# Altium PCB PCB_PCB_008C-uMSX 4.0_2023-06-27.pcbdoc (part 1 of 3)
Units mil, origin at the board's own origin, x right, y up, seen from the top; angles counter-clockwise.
Board outline 14478.11 x 5217.07 mil, 2 copper layers (Top Layer, Bottom Layer); 184 components, 339 nets, 1501 pads, 946 vias.
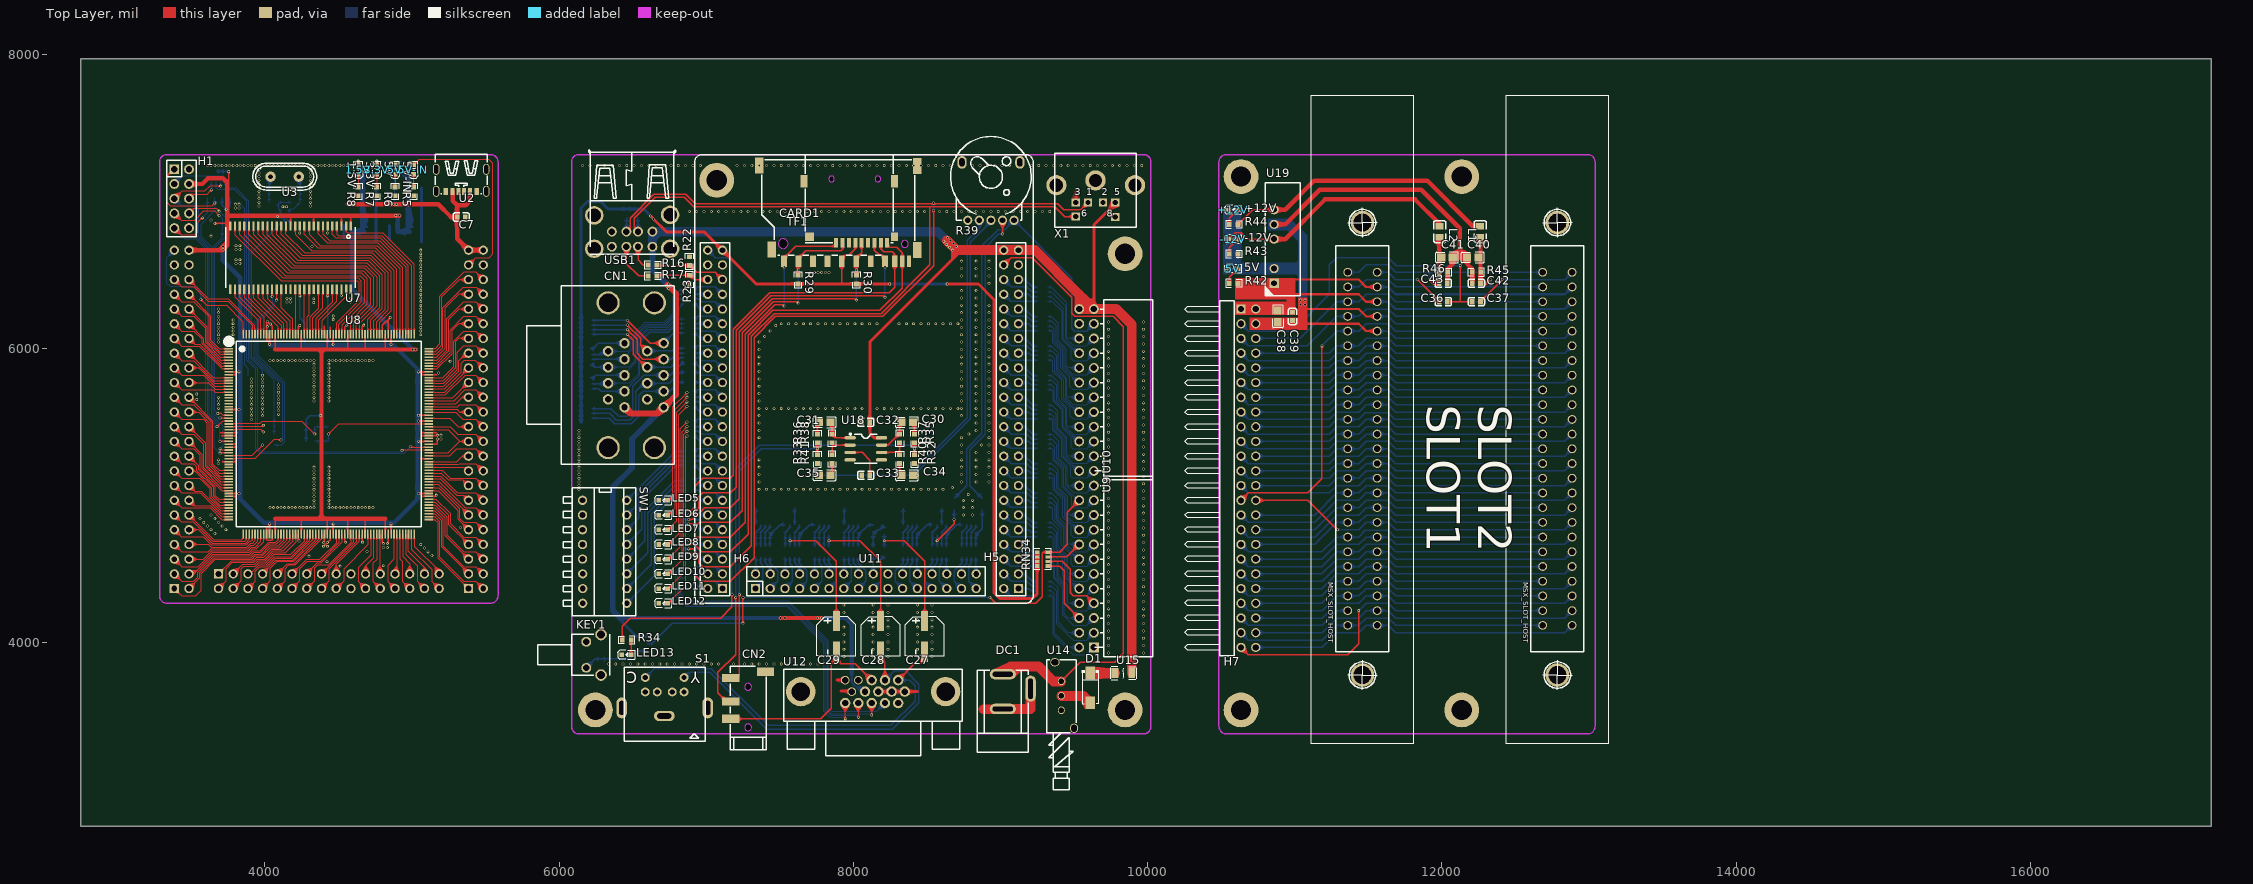
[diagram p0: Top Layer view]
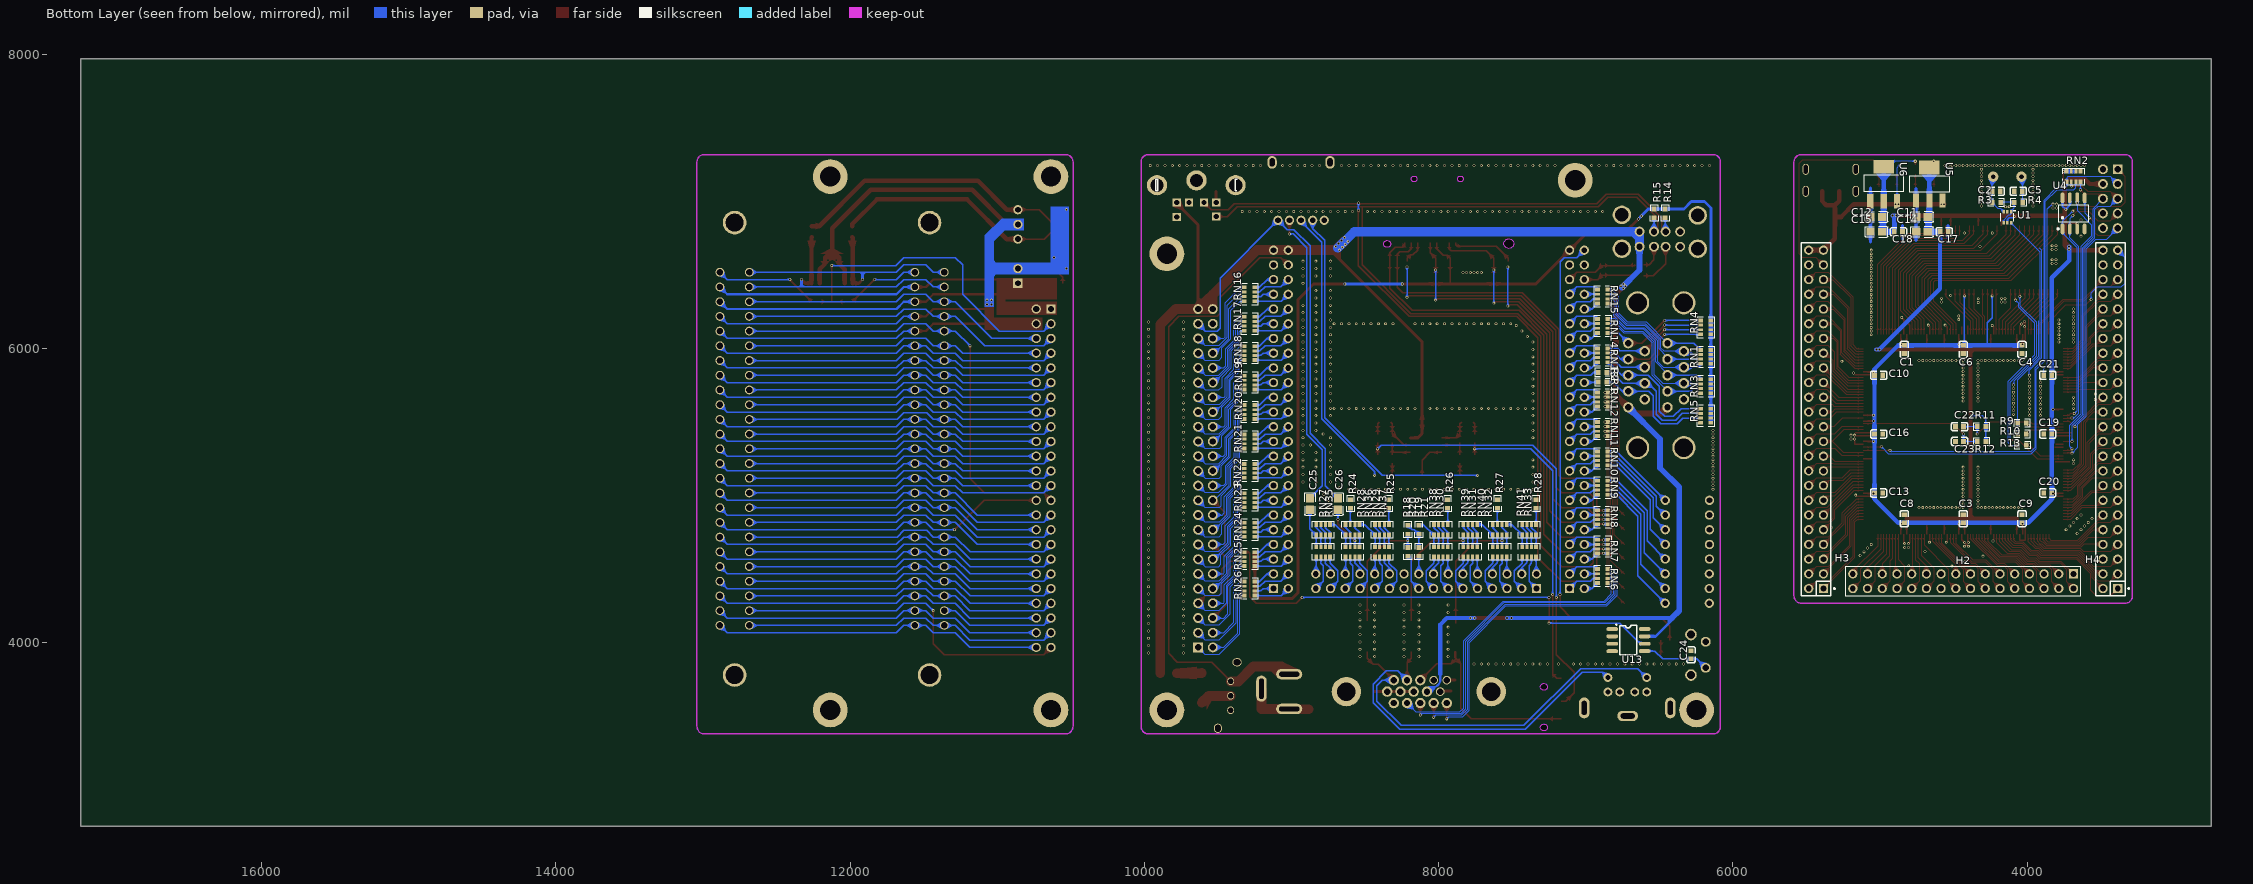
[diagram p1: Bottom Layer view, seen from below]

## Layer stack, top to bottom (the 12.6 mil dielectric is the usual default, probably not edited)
Top Layer: signal copper (thickness not stored)
Dielectric: dielectric 12.6, FR-4, Dk 4.8
Bottom Layer: signal copper (thickness not stored)

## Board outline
17228.11,2750 2750,2750 2750,7967.07 17228.11,7967.07

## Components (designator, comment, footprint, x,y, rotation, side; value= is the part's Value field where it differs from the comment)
1.5V "LED_0603-R" LED_0603 4635,7217.05 r90 top
3.3V "LED_0603-R" LED_0603 4760,7217.05 r90 top
5V "LED_0603-R" LED_0603 4885,7217.05 r90 top
5V "LED_0603-R" LED_0603 10585,6542.05 r0 top
5V-IN "LED_0603-R" LED_0603 5010,7217.05 r90 top
+12V "LED_0603-R" LED_0603 10585,6942.05 r0 top
-12V "LED_0603-R" LED_0603 10585,6742.05 r0 top
C1 "CC0603KRX7R9BB104" C0603 4835,5992.05 r90 bottom
C2 "CC0603JRNPO9BN270" C0603 4210,7067.05 r0 bottom
C3 "CC0603KRX7R9BB104" C0603 4435,4842.05 r270 bottom
C4 "CC0603KRX7R9BB104" C0603 4035,5992.05 r90 bottom
C5 "CC0603JRNPO9BN270" C0603 4060,7067.05 r180 bottom
C6 "CC0603KRX7R9BB104" C0603 4435,5992.05 r90 bottom
C7 "0603B104K500NT" C0603 5335,6892.05 r180 top
C8 "CC0603KRX7R9BB104" C0603 4835,4842.05 r270 bottom
C9 "CC0603KRX7R9BB104" C0603 4035,4842.05 r270 bottom
C10 "CC0603KRX7R9BB104" C0603 5010,5817.05 r0 bottom
C11 "CL21A476MQYNNNE" C0805 4715,6892.05 r180 bottom
C12 "CL21A476MQYNNNE" C0805 5025,6892.05 r180 bottom
C13 "CC0603KRX7R9BB104" C0603 5010,5017.05 r0 bottom
C14 "CL21A476MQYNNNE" C0805 4715,6792.05 r180 bottom
C15 "CL21A476MQYNNNE" C0805 5025,6792.05 r180 bottom
C16 "CC0603KRX7R9BB104" C0603 5010,5417.05 r0 bottom
C17 "0603B104K500NT" C0603 4565,6792.05 r0 bottom
C18 "0603B104K500NT" C0603 4875,6792.05 r0 bottom
C19 "CC0603KRX7R9BB104" C0603 3860,5417.05 r180 bottom
C20 "CC0603KRX7R9BB104" C0603 3860,5017.05 r180 bottom
C21 "CC0603KRX7R9BB104" C0603 3860,5817.05 r180 bottom
C22 "0.1UF" C0603 4460,5467.05 r0 bottom
C23 "0.1UF" C0603 4460,5367.05 r0 bottom
C24 "UMK107BBJ225KA-T" C0603 6285,3917.05 r90 bottom
C25 "CL21A476MQYNNNE" C0805 8875,4942.05 r270 bottom
C26 "CL21A476MQYNNNE" C0805 8685,4942.05 r270 bottom
C27 "固态电容220uF/10V6.3*5.4" CAP-SMD_BD6.3-L6.6-W6.6-LS7.2-FD 8485,4042.05 r270 top
C28 "固态电容220uF/10V6.3*5.4" CAP-SMD_BD6.3-L6.6-W6.6-LS7.2-FD 8185,4042.05 r270 top
C29 "固态电容220uF/10V6.3*5.4" CAP-SMD_BD6.3-L6.6-W6.6-LS7.2-FD 7885,4042.05 r270 top
C30 "CL21A476MQYNNNE" C0805 8365,5497.05 r0 top
C31 "CL21A476MQYNNNE" C0805 7805,5497.05 r0 top
C32 "CC0603KRX7R9BB104" C0603 8085,5497.05 r0 top
C33 "CC0603KRX7R9BB104" C0603 8085,5137.05 r180 top
C34 "CL21A476MQYNNNE" C0805 8365,5137.05 r0 top
C35 "CL21A476MQYNNNE" C0805 7805,5137.05 r0 top
C36 "CAP_0603" C0603 12010,6317.05 r180 top
C37 "CAP_0603" C0603 12235,6317.05 r0 top
C38 "CL21A476MQYNNNE" C0805 10885,6217.05 r90 top
C39 "CAP_0603" C0603 10985,6217.05 r90 top
C40 "CL21A476MQYNNNE" C0805 12210,6617.05 r0 top
C41 "CL21A476MQYNNNE" C0805 12035,6617.05 r0 top
C42 "CAP_0603" C0603 12235,6442.05 r0 top
C43 "CAP_0603" C0603 12010,6442.05 r180 top
CARD1 "SD-101" SD-SMD_SD-101 7897.01,6917.05 r180 top
CN1 "HYC33-VGA18A-158" DSUB-TH_HYC33-VGA18A-158 6522.01,5817.05 r270 top
CN2 "PJ-320D_C431535" AUDIO-SMD_PJ-320D 7285,3642.05 r180 top
D1 "SS14_C2480" SMA_L4.2-W2.6-LS5.3-RD 9610,3692.05 r270 top
DC1 "DC-005" DC-IN-TH_DC-005-A 9110,3667.05 r90 top
H1 "排母2.54mm2*5p 直" HDR-TH_10P-P2.54-V-F-R2-C5-S2.54 3435,7017.05 r270 top
H2 "B-2100S32P-B110" HDR-TH_32P-P2.54-V-M-R2-C16-S2.54 4435,4417.05 r0 bottom
H3 "X6521WV-2x24H-C60D30" HDR-TH_48P-2.54-V-M-R2-C24-S2.54 5435,5517.05 r90 bottom
H4 "X6521WV-2x24H-C60D30" HDR-TH_48P-2.54-V-M-R2-C24-S2.54 3435,5517.05 r90 bottom
H5 "X5521FV-2x24-C70D30-1000" HDR-TH_48P-P2.54-V-F-R2-C24-S2.54 9072.01,5517.05 r90 top
H6 "X5521FV-2x24-C70D30-1000" HDR-TH_48P-P2.54-V-F-R2-C24-S2.54 7060,5517.05 r90 top
H7 "X6521WR-2x24H-C30D60" HDR-TH_48P-P2.54-H-M-R2-C24-S2.54 10685,5117.05 r270 top
KEY1 "1-1825027-1" KEY-TH_1-1825027-1 6235,3917.05 r270 top
L1 "A-6-9007-2" L0805 12260,6792.05 r270 top
L2 "A-6-9007-2" L0805 11985,6792.05 r270 top
LED5 "LED_0603-R" LED_0603 6710,4967.05 r0 top
LED6 "LED_0603-R" LED_0603 6710,4867.05 r0 top
LED7 "LED_0603-R" LED_0603 6710,4767.05 r0 top
LED8 "LED_0603-R" LED_0603 6710,4667.05 r0 top
LED9 "LED_0603-R" LED_0603 6710,4567.05 r0 top
LED10 "LED_0603-R" LED_0603 6710,4467.05 r0 top
LED11 "LED_0603-R" LED_0603 6710,4367.05 r0 top
LED12 "LED_0603-R" LED_0603 6710,4267.05 r0 top
LED13 "LED_0603-R" LED_0603 6460,3917.05 r0 top
R1 "Res_0603" R0603 6885,5772.05 r0 bottom
R2 "Res_0603" R0603 6885,5837.05 r0 bottom
R3 "0603WAF1004T5E" R0603 4210,6992.05 r180 bottom
R4 "0603WAF1000T5E" R0603 4060,6992.05 r0 bottom
R5 "0603WAF3301T5E" R0603_NEW 5010,7067.05 r270 top
R6 "0603WAF3301T5E" R0603_NEW 4885,7067.05 r270 top
R7 "0603WAF3301T5E" R0603_NEW 4760,7067.05 r270 top
R8 "0603WAF3301T5E" R0603_NEW 4635,7067.05 r270 top
R9 "0603WAF1000T5E" R0603 4035,5492.05 r180 bottom
R10 "0603WAF1000T5E" R0603 4035,5417.05 r180 bottom
R11 "0603WAF1000T5E" R0603 4310,5467.05 r180 bottom
R12 "0603WAF1000T5E" R0603 4310,5367.05 r180 bottom
R13 "Res_0603" R0603 4035,5342.05 r0 bottom
R14 "0603WAF1001T5E" R0603 6460,6917.05 r90 bottom
R15 "0603WAF1001T5E" R0603 6535,6917.05 r90 bottom
R16 "0603WAF330JT5E" R0603 6635,6567.05 r180 top
R17 "0603WAF330JT5E" R0603 6635,6492.05 r180 top
R18 "Res_0603" R0603 8210,4617.05 r90 bottom
R19 "Res_0603" R0603 8135,4617.05 r90 bottom
R20 "Res_0603" R0603 8210,4767.05 r90 bottom
R21 "Res_0603" R0603 8135,4767.05 r90 bottom
R22 "0603WAF1502T5E" R0603 6885,6592.05 r270 top
R23 "0603WAF1502T5E" R0603 6885,6467.05 r90 top
R24 "0603WAF1000T5E" R0603 8600,4942.05 r90 bottom
R25 "0603WAF1000T5E" R0603 8340,4942.05 r90 bottom
R26 "0603WAF1000T5E" R0603 7940,4942.05 r90 bottom
R27 "0603WAF1000T5E" R0603 7600,4942.05 r90 bottom
R28 "0603WAF1000T5E" R0603 7340,4942.05 r90 bottom
R29 "0603WAF1002T5E" R0603 7625,6467.05 r270 top
R30 "0603WAF1002T5E" R0603 8020,6467.05 r270 top
R32 "0603WAF1002T5E" R0603 8415,5247.05 r270 top
R33 "0603WAF1002T5E" R0603 7755,5247.05 r270 top
R34 "0603WAF1001T5E" R0603 6460,4017.05 r0 top
R35 "0603WAF100JT5E" R0603 8415,5387.05 r270 top
R36 "0603WAF100JT5E" R0603 7755,5387.05 r270 top
R37 "0603WAF1502T5E" R0603 8315,5387.05 r90 top
R38 "0603WAF1502T5E" R0603 7855,5387.05 r90 top
R39 "RK10J12E0024" RES-TH_RK10J12E002L 8935,7067.05 r0 top
R40 "0603WAF1002T5E" R0603 8315,5247.05 r270 top
R41 "0603WAF1002T5E" R0603 7855,5247.05 r90 top
R42 "0603WAF1001T5E" R0603 10585,6442.05 r180 top
R43 "0603WAF1001T5E" R0603 10585,6642.05 r180 top
R44 "0603WAF1001T5E" R0603 10585,6842.05 r180 top
R45 "0603WAF2001T5E" R0603 12235,6517.05 r0 top
R46 "0603WAF2001T5E" R0603 12010,6517.05 r180 top
RN1 "4D03WGJ0101T5E" RES-ARRAY-SMD_0603-8P-L3.2-W1.6-BL 6185,5942.05 r90 bottom
RN2 "4D03WGJ0101T5E" RES-ARRAY-SMD_0603-8P-L3.2-W1.6-BL 3685,7167.05 r180 bottom
RN3 "4D03WGJ0101T5E" RES-ARRAY-SMD_0603-8P-L3.2-W1.6-BL 6185,5742.05 r90 bottom
RN4 "4D03WGJ0101T5E" RES-ARRAY-SMD_0603-8P-L3.2-W1.6-BL 6185,6142.05 r270 bottom
RN5 "4D03WGJ0101T5E" RES-ARRAY-SMD_0603-8P-L3.2-W1.6-BL 6185,5542.05 r270 bottom
RN6 "4D03WGJ0101T5E" RES-ARRAY-SMD_0603-8P-L3.2-W1.6-BL 6885,4452.05 r270 bottom
RN7 "4D03WGJ0101T5E" RES-ARRAY-SMD_0603-8P-L3.2-W1.6-BL 6885,4652.05 r270 bottom
RN8 "4D03WGJ0101T5E" RES-ARRAY-SMD_0603-8P-L3.2-W1.6-BL 6885,4852.05 r270 bottom
RN9 "4D03WGJ0101T5E" RES-ARRAY-SMD_0603-8P-L3.2-W1.6-BL 6885,5052.05 r270 bottom
RN10 "4D03WGJ0101T5E" RES-ARRAY-SMD_0603-8P-L3.2-W1.6-BL 6885,5252.05 r270 bottom
RN11 "4D03WGJ0101T5E" RES-ARRAY-SMD_0603-8P-L3.2-W1.6-BL 6885,5452.05 r270 bottom
RN12 "4D03WGJ0101T5E" RES-ARRAY-SMD_0603-8P-L3.2-W1.6-BL 6885,5652.05 r270 bottom
RN13 "4D03WGJ0101T5E" RES-ARRAY-SMD_0603-8P-L3.2-W1.6-BL 6885,5952.05 r270 bottom
RN14 "4D03WGJ0101T5E" RES-ARRAY-SMD_0603-8P-L3.2-W1.6-BL 6885,6152.05 r270 bottom
RN15 "4D03WGJ0101T5E" RES-ARRAY-SMD_0603-8P-L3.2-W1.6-BL 6885,6352.05 r270 bottom
RN16 "4D03WGJ0101T5E" RES-ARRAY-SMD_0603-8P-L3.2-W1.6-BL 9285,6367.05 r90 bottom
RN17 "4D03WGJ0101T5E" RES-ARRAY-SMD_0603-8P-L3.2-W1.6-BL 9285,6167.05 r90 bottom
RN18 "4D03WGJ0101T5E" RES-ARRAY-SMD_0603-8P-L3.2-W1.6-BL 9285,5967.05 r90 bottom
RN19 "4D03WGJ0101T5E" RES-ARRAY-SMD_0603-8P-L3.2-W1.6-BL 9285,5767.05 r90 bottom
RN20 "4D03WGJ0101T5E" RES-ARRAY-SMD_0603-8P-L3.2-W1.6-BL 9285,5567.05 r90 bottom
RN21 "4D03WGJ0101T5E" RES-ARRAY-SMD_0603-8P-L3.2-W1.6-BL 9285,5367.05 r90 bottom
RN22 "4D03WGJ0101T5E" RES-ARRAY-SMD_0603-8P-L3.2-W1.6-BL 9285,5167.05 r90 bottom
RN23 "4D03WGJ0101T5E" RES-ARRAY-SMD_0603-8P-L3.2-W1.6-BL 9285,4967.05 r90 bottom
RN24 "4D03WGJ0101T5E" RES-ARRAY-SMD_0603-8P-L3.2-W1.6-BL 9285,4767.05 r90 bottom
RN25 "4D03WGJ0101T5E" RES-ARRAY-SMD_0603-8P-L3.2-W1.6-BL 9285,4567.05 r90 bottom
RN26 "4D03WGJ0101T5E" RES-ARRAY-SMD_0603-8P-L3.2-W1.6-BL 9285,4367.05 r90 bottom
RN27 "4D03WGJ0101T5E" RES-ARRAY-SMD_0603-8P-L3.2-W1.6-BL 8785,4617.05 r180 bottom
RN28 "4D03WGJ0101T5E" RES-ARRAY-SMD_0603-8P-L3.2-W1.6-BL 8585,4617.05 r180 bottom
RN29 "4D03WGJ0101T5E" RES-ARRAY-SMD_0603-8P-L3.2-W1.6-BL 8385,4617.05 r180 bottom
RN30 "4D03WGJ0101T5E" RES-ARRAY-SMD_0603-8P-L3.2-W1.6-BL 7985,4617.05 r180 bottom
RN31 "4D03WGJ0101T5E" RES-ARRAY-SMD_0603-8P-L3.2-W1.6-BL 7785,4617.05 r180 bottom
RN32 "4D03WGJ0101T5E" RES-ARRAY-SMD_0603-8P-L3.2-W1.6-BL 7585,4617.05 r180 bottom
RN33 "4D03WGJ0101T5E" RES-ARRAY-SMD_0603-8P-L3.2-W1.6-BL 7385,4617.05 r180 bottom
RN34 "4D03WGJ0101T5E" RES-ARRAY-SMD_0603-8P-L3.2-W1.6-BL 9285,4567.05 r90 top
RN35 "4D03WGJ0101T5E" RES-ARRAY-SMD_0603-8P-L3.2-W1.6-BL 8785,4767.05 r180 bottom
RN36 "4D03WGJ0101T5E" RES-ARRAY-SMD_0603-8P-L3.2-W1.6-BL 8585,4767.05 r180 bottom
RN37 "4D03WGJ0101T5E" RES-ARRAY-SMD_0603-8P-L3.2-W1.6-BL 8385,4767.05 r180 bottom
RN38 "4D03WGJ0101T5E" RES-ARRAY-SMD_0603-8P-L3.2-W1.6-BL 7985,4767.05 r180 bottom
RN39 "4D03WGJ0101T5E" RES-ARRAY-SMD_0603-8P-L3.2-W1.6-BL 7785,4767.05 r180 bottom
RN40 "4D03WGJ0101T5E" RES-ARRAY-SMD_0603-8P-L3.2-W1.6-BL 7585,4767.05 r180 bottom
RN41 "4D03WGJ0101T5E" RES-ARRAY-SMD_0603-8P-L3.2-W1.6-BL 7385,4767.05 r180 bottom
S1 "S端子母座" S端子母座 6710,3567.05 r180 top
SLOT1 "MSX_SLOT_HOST" CONN_EDGE_50P 11460,5317.05 r270 top
SLOT2 "MSX_SLOT_HOST" CONN_EDGE_50P 12785,5317.05 r270 top
SW1 "DP-08BP" SW-TH_DP-08XP 6310,4617.05 r270 top
TF1 "TF-012" TF-SMD_TF-012 7972.01,6927.05 r180 top
U1 "NC7WZU04P6X" SC-70-6_L2.2-W1.3-P0.65-LS2.1-BR 4135,6892.05 r90 bottom
U2 "USB-TYPE-C-009" TYPE-C-SMD_TYPE-C-6P 5335,7142.05 r180 top
U3 "ECS-214.7-S-4" HC-49US_L11.0-W4.6-P4.88 4135,7167.05 r180 top
U4 "EPCS4-SO8" SOP-8_L4.9-W3.9-P1.27-LS6.0-BL 3685,6917.05 r180 bottom
U5 "AMS1117-1.5_C963403" SOT-223_L6.3-W3.5-P2.30-LS7.0-BR 4665,7117.05 r270 bottom
U6 "AMS1117-3.3_C6186" SOT-223-3_L6.5-W3.4-P2.30-LS7.0-BR 4975,7117.05 r270 bottom
U7 "MT48LC16M" TSOP54 4175,6617.05 r180 top
U8 "EP1C12Q240C8N" MQFP-240_L32.0-W32.0-P0.50-LS34.6-BL 4435,5417.05 r270 top
U9 "PM254-2-12-W-8.5" HDR-TH_24P-P2.54-H-F-R2-C12-W8.5 9585,4517.05 r90 top
U10 "PM254-2-12-W-8.5" hdr-th_24p-p2.54-h-f-r2-c12-w8.5 9585,5717.05 r90 top
U11 "PM254-2-16-Z-8.5" HDR-TH_32P-P2.54-V-F-R2-C16-S2.54 8085,4417.05 r0 top
U12 "VGAS-C" DB15-TH_FDB1519-F0DB300U1KA 8135,3667.05 r0 top
U13 "M51953BFP" SOP-8_L4.9-W3.8-P1.27-LS6.0-BL 6710,4017.05 r270 bottom
U14 "PS-12E051" SW-TH_PS-12E051XX 9435,3642.05 r270 top
U15 "PTC1206SMD1206P010TF0.1A/60V" F1206 9835,3792.05 r0 top
U18 "TPA6111A2DR" SOIC-8_L5.0-W4.0-P1.27-LS6.0-BL 8085,5317.05 r270 top
U19 "A0512S-1W" PWRM-TH_7P-L19.5-W6.0-P2.54-PE3_7 10860,6692.05 r90 top
USB1 "907-111A1022D10200" USB-A-TH_USB-M-51 6497.01,6792.05 r180 top
X1 "MINI_DIN_6" M_DIN6 9647.01,7017.05 r0 top

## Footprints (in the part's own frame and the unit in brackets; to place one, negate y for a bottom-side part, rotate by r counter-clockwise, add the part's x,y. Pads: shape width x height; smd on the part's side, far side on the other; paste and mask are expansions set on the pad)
AUDIO-SMD_PJ-320D [mm]
  rect 3x1.4 smd: 1(-3,-4.05) 2(3,4.05) 3(3,1.05) 4(3,-2.95)
  Multi-Layer board cut-out: -0.6,-1.45 -0.518,-1.748 -0.298,-1.965 0,-2.045 0.298,-1.965 0.518,-1.748 0.6,-1.45 0.6,-1.45 0.518,-1.152 0.298,-0.935 0,-0.856 -0.298,-0.935 -0.518,-1.152 -0.6,-1.45
  Multi-Layer board cut-out: -0.6,5.55 -0.518,5.252 -0.298,5.035 0,4.955 0.298,5.035 0.518,5.252 0.6,5.55 0.6,5.55 0.518,5.848 0.298,6.065 0,6.144 -0.298,6.065 -0.518,5.848 -0.6,5.55
  Multi-Layer keep-out region: -0.6,-1.45 -0.518,-1.748 -0.298,-1.965 0,-2.045 0.298,-1.965 0.518,-1.748 0.6,-1.45 0.6,-1.45 0.518,-1.152 0.298,-0.935 0,-0.856 -0.298,-0.935 -0.518,-1.152 -0.6,-1.45
  Multi-Layer keep-out region: -0.6,5.55 -0.518,5.252 -0.298,5.035 0,4.955 0.298,5.035 0.518,5.252 0.6,5.55 0.6,5.55 0.518,5.848 0.298,6.065 0,6.144 -0.298,6.065 -0.518,5.848 -0.6,5.55
  silkscreen extent -3.12,-4.98 3.13,9.37
C0603 [mm]
  rect 0.8x0.9 smd: 1(-0.7,0) 2(0.7,0)
  silkscreen extent -1.41,-0.71 1.39,0.72
C0805 [mm]
  rect 1.41x1.35 smd: 1(-1,0) 2(1,0)
  silkscreen extent -1.96,-0.9 1.96,0.9
CAP-SMD_BD6.3-L6.6-W6.6-LS7.2-FD [mm]
  rect 3.5x1.2 smd: 1(-2.67,0) 2(2.67,0)
  silkscreen extent -3.38,-3.38 3.38,3.38
CONN_EDGE_50P [mil]
  round 160 hole 120 slot 120.2 at 0 deg: 0(-1537.52,0) 0(1537.47,0)
  round 60 hole 40 slot 40.2 at 0 deg: 1(1199.97,100) 2(1199.97,-100) 3(1099.97,100) 4(1099.97,-100) 5(999.97,100) 6(999.97,-100) 7(899.97,100) 8(899.97,-100) 9(799.97,100) 10(799.97,-100) 11(699.97,100) 12(699.97,-100) 13(599.97,100) 14(599.97,-100) 15(499.97,100) 16(499.97,-100) 17(399.97,100) 18(399.97,-100) 19(299.97,100) 20(299.97,-100) 21(199.97,100) 22(199.97,-100) 23(99.97,100) 24(99.97,-100) 25(-0.03,100) 26(-0.03,-100) 27(-100.02,100) 28(-100.02,-100) 29(-200.02,100) 30(-200.02,-100) 31(-300.02,100) 32(-300.02,-100) 33(-400.02,100) 34(-400.02,-100) 35(-500.02,100) 36(-500.02,-100) 37(-600.02,100) 38(-600.02,-100) 39(-700.02,100) 40(-700.02,-100) 41(-800.02,100) 42(-800.02,-100) 43(-900.02,100) 44(-900.02,-100) 45(-1000.02,100) 46(-1000.02,-100) 47(-1100.02,100) 48(-1100.02,-100) 49(-1200.02,100) 50(-1200.02,-100)
  silkscreen extent -2400,-350 2000,350
DB15-TH_FDB1519-F0DB300U1KA [mm]
  round 5.08 hole 3.2: 0(-12.495,0) 0(12.495,0)
  round 1.8 hole 1.1: 1(4.315,1.98) 2(2.025,1.98) 3(-0.265,1.98) 6(5.46,0) 7(3.17,0) 8(0.88,0) 9(-1.41,0) 11(4.315,-1.98) 12(2.025,-1.98) 13(-0.265,-1.98) 14(-2.555,-1.98) 15(-4.845,-1.98)
  round 1.5 hole 1.1: 4(-2.555,1.98) 5(-4.845,1.98) 10(-3.7,0)
  silkscreen extent -15.4,-11.1 15.4,3.85
DC-IN-TH_DC-005-A [mm]
  oval 1.8x4.5 hole 0.8 slot 3.5 at 90 deg: 1(3,2.4) 2(-3,2.4)
  oval 4.5x1.8 hole 0.8 slot 3.5 at 0 deg: 3(0.5,-2.4)
  silkscreen extent -10.5,-2 3.7,6.8
DSUB-TH_HYC33-VGA18A-158 [mm]
  round 1.8 hole 1.1: 1(-5.54,-1.96) 2(-2.77,-1.96) 3(0,-1.96) 4(2.77,-1.96) 5(5.54,-1.96) 6(-4.155,-4.8) 7(-1.385,-4.8) 8(1.385,-4.8) 9(4.155,-4.8) 10(-5.54,4.8) 11(-2.77,4.8) 12(0,4.8) 13(2.77,4.8) 14(5.54,4.8) 15(-4.155,1.96) 16(-1.385,1.96) 17(1.385,1.96) 18(4.155,1.96)
  round 4 hole 3.2: 19(-12.5,3.2) 20(12.5,3.2) 21(-12.5,-4.8) 22(12.5,-4.8)
  silkscreen extent -15.4,-18.9 15.4,6.6
F1206 [mm]
  rect 1.19x1.728 smd: 1(-1.445,0) 2(1.445,0)
  silkscreen extent -2.27,-1.09 2.27,1.09
HC-49US_L11.0-W4.6-P4.88 [mm]
  round 1.8 hole 0.8: 1(-2.44,0) 2(2.44,0)
  silkscreen extent -5.51,-2.32 5.51,2.32
HDR-TH_10P-P2.54-V-F-R2-C5-S2.54 [mm]
  rect 1.575x1.7 hole 1.1: 1(-5.08,-1.27)
  round 1.7 hole 1.1: 2(-5.08,1.27) 3(-2.54,-1.27) 4(-2.54,1.27) 5(0,-1.27) 6(0,1.27) 7(2.54,-1.27) 8(2.54,1.27) 9(5.08,-1.27) 10(5.08,1.27)
  silkscreen extent -6.6,-2.54 6.6,2.54
HDR-TH_24P-P2.54-H-F-R2-C12-W8.5 [mm]
  rect 1.7x1.7 hole 1.1: 1(-13.97,-1.27)
  round 1.7 hole 1.1: 2(-13.97,1.27) 3(-11.43,-1.27) 4(-11.43,1.27) 5(-8.89,-1.27) 6(-8.89,1.27) 7(-6.35,-1.27) 8(-6.35,1.27) 9(-3.81,-1.27) 10(-3.81,1.27) 11(-1.27,-1.27) 12(-1.27,1.27) 13(1.27,-1.27) 14(1.27,1.27) 15(3.81,-1.27) 16(3.81,1.27) 17(6.35,-1.27) 18(6.35,1.27) 19(8.89,-1.27) 20(8.89,1.27) 21(11.43,-1.27) 22(11.43,1.27) 23(13.97,-1.27) 24(13.97,1.27)
  silkscreen extent -15.54,-11.43 15.54,-1.4
hdr-th_24p-p2.54-h-f-r2-c12-w8.5 [mm]
  round 1.7 hole 1.1: 1(-13.97,-1.27) 2(-13.97,1.27) 3(-11.43,-1.27) 4(-11.43,1.27) 5(-8.89,-1.27) 6(-8.89,1.27) 7(-6.35,-1.27) 8(-6.35,1.27) 9(-3.81,-1.27) 10(-3.81,1.27) 11(-1.27,-1.27) 12(-1.27,1.27) 13(1.27,-1.27) 14(1.27,1.27) 15(3.81,-1.27) 16(3.81,1.27) 17(6.35,-1.27) 18(6.35,1.27) 19(8.89,-1.27) 20(8.89,1.27) 21(11.43,-1.27) 22(11.43,1.27) 23(13.97,-1.27) 24(13.97,1.27)
  silkscreen extent -15.54,-11.43 15.54,-1.4
HDR-TH_32P-P2.54-V-F-R2-C16-S2.54 [mm]
  rect 1.6x1.6 hole 1: 1(-19.05,-1.27)
  round 1.6 hole 1: 2(-19.05,1.27) 3(-16.51,-1.27) 4(-16.51,1.27) 5(-13.97,-1.27) 6(-13.97,1.27) 7(-11.43,-1.27) 8(-11.43,1.27) 9(-8.89,-1.27) 10(-8.89,1.27) 11(-6.35,-1.27) 12(-6.35,1.27) 13(-3.81,-1.27) 14(-3.81,1.27) 15(-1.27,-1.27) 16(-1.27,1.27) 17(1.27,-1.27) 18(1.27,1.27) 19(3.81,-1.27) 20(3.81,1.27) 21(6.35,-1.27) 22(6.35,1.27) 23(8.89,-1.27) 24(8.89,1.27) 25(11.43,-1.27) 26(11.43,1.27) 27(13.97,-1.27) 28(13.97,1.27) 29(16.51,-1.27) 30(16.51,1.27) 31(19.05,-1.27) 32(19.05,1.27)
  silkscreen extent -20.57,-2.54 20.57,2.54
HDR-TH_32P-P2.54-V-M-R2-C16-S2.54 [mm]
  rect 1.6x1.6 hole 1: 1(-19.05,-1.27)
  round 1.6 hole 1: 2(-19.05,1.27) 3(-16.51,-1.27) 4(-16.51,1.27) 5(-13.97,-1.27) 6(-13.97,1.27) 7(-11.43,-1.27) 8(-11.43,1.27) 9(-8.89,-1.27) 10(-8.89,1.27) 11(-6.35,-1.27) 12(-6.35,1.27) 13(-3.81,-1.27) 14(-3.81,1.27) 15(-1.27,-1.27) 16(-1.27,1.27) 17(1.27,-1.27) 18(1.27,1.27) 19(3.81,-1.27) 20(3.81,1.27) 21(6.35,-1.27) 22(6.35,1.27) 23(8.89,-1.27) 24(8.89,1.27) 25(11.43,-1.27) 26(11.43,1.27) 27(13.97,-1.27) 28(13.97,1.27) 29(16.51,-1.27) 30(16.51,1.27) 31(19.05,-1.27) 32(19.05,1.27)
  silkscreen extent -20.32,-2.54 20.32,2.54
HDR-TH_48P-2.54-V-M-R2-C24-S2.54 [mm]
  rect 1.6x1.6 hole 1: 1(-29.21,-1.27)
  round 1.6 hole 1: 2(-29.21,1.27) 3(-26.67,-1.27) 4(-26.67,1.27) 5(-24.13,-1.27) 6(-24.13,1.27) 7(-21.59,-1.27) 8(-21.59,1.27) 9(-19.05,-1.27) 10(-19.05,1.27) 11(-16.51,-1.27) 12(-16.51,1.27) 13(-13.97,-1.27) 14(-13.97,1.27) 15(-11.43,-1.27) 16(-11.43,1.27) 17(-8.89,-1.27) 18(-8.89,1.27) 19(-6.35,-1.27) 20(-6.35,1.27) 21(-3.81,-1.27) 22(-3.81,1.27) 23(-1.27,-1.27) 24(-1.27,1.27) 25(1.27,-1.27) 26(1.27,1.27) 27(3.81,-1.27) 28(3.81,1.27) 29(6.35,-1.27) 30(6.35,1.27) 31(8.89,-1.27) 32(8.89,1.27) 33(11.43,-1.27) 34(11.43,1.27) 35(13.97,-1.27) 36(13.97,1.27) 37(16.51,-1.27) 38(16.51,1.27) 39(19.05,-1.27) 40(19.05,1.27) 41(21.59,-1.27) 42(21.59,1.27) 43(24.13,-1.27) 44(24.13,1.27) 45(26.67,-1.27) 46(26.67,1.27) 47(29.21,-1.27) 48(29.21,1.27)
  silkscreen extent -30.48,-3.3 30.48,2.54
HDR-TH_48P-P2.54-H-M-R2-C24-S2.54 [mm]
  rect 1.6x1.6 hole 1.05: 1(-29.21,-1.27)
  round 1.6 hole 1.05: 2(-29.21,1.27) 3(-26.67,-1.27) 4(-26.67,1.27) 5(-24.13,-1.27) 6(-24.13,1.27) 7(-21.59,-1.27) 8(-21.59,1.27) 9(-19.05,-1.27) 10(-19.05,1.27) 11(-16.51,-1.27) 12(-16.51,1.27) 13(-13.97,-1.27) 14(-13.97,1.27) 15(-11.43,-1.27) 16(-11.43,1.27) 17(-8.89,-1.27) 18(-8.89,1.27) 19(-6.35,-1.27) 20(-6.35,1.27) 21(-3.81,-1.27) 22(-3.81,1.27) 23(-1.27,-1.27) 24(-1.27,1.27) 25(1.27,-1.27) 26(1.27,1.27) 27(3.81,-1.27) 28(3.81,1.27) 29(6.35,-1.27) 30(6.35,1.27) 31(8.89,-1.27) 32(8.89,1.27) 33(11.43,-1.27) 34(11.43,1.27) 35(13.97,-1.27) 36(13.97,1.27) 37(16.51,-1.27) 38(16.51,1.27) 39(19.05,-1.27) 40(19.05,1.27) 41(21.59,-1.27) 42(21.59,1.27) 43(24.13,-1.27) 44(24.13,1.27) 45(26.67,-1.27) 46(26.67,1.27) 47(29.21,-1.27) 48(29.21,1.27)
  silkscreen extent -30.67,-10.97 30.67,-2.47
HDR-TH_48P-P2.54-V-F-R2-C24-S2.54 [mm]
  rect 1.6x1.6 hole 1: 1(-29.21,-1.27)
  round 1.6 hole 1: 2(-29.21,1.27) 3(-26.67,-1.27) 4(-26.67,1.27) 5(-24.13,-1.27) 6(-24.13,1.27) 7(-21.59,-1.27) 8(-21.59,1.27) 9(-19.05,-1.27) 10(-19.05,1.27) 11(-16.51,-1.27) 12(-16.51,1.27) 13(-13.97,-1.27) 14(-13.97,1.27) 15(-11.43,-1.27) 16(-11.43,1.27) 17(-8.89,-1.27) 18(-8.89,1.27) 19(-6.35,-1.27) 20(-6.35,1.27) 21(-3.81,-1.27) 22(-3.81,1.27) 23(-1.27,-1.27) 24(-1.27,1.27) 25(1.27,-1.27) 26(1.27,1.27) 27(3.81,-1.27) 28(3.81,1.27) 29(6.35,-1.27) 30(6.35,1.27) 31(8.89,-1.27) 32(8.89,1.27) 33(11.43,-1.27) 34(11.43,1.27) 35(13.97,-1.27) 36(13.97,1.27) 37(16.51,-1.27) 38(16.51,1.27) 39(19.05,-1.27) 40(19.05,1.27) 41(21.59,-1.27) 42(21.59,1.27) 43(24.13,-1.27) 44(24.13,1.27) 45(26.67,-1.27) 46(26.67,1.27) 47(29.21,-1.27) 48(29.21,1.27)
  silkscreen extent -30.48,-2.54 30.48,2.54
KEY-TH_1-1825027-1 [mm]
  round 2 hole 1.4: 0(-3.5,1.27) 0(3.5,1.27)
  round 1.7 hole 1.1: 1(-2.25,-1.27) 2(2.25,-1.27)
  silkscreen extent -3.56,-9.63 3.56,2.79
L0805 [mil]
  rect 44.59x54.21 smd: 1(-38.04,0) 2(38.04,0)
  silkscreen extent -77,-40 73,40
LED_0603 [mil]
  rect 31.5x31.5 smd: 1(-33.5,-0.4) 2(29.5,-0.2)
  silkscreen extent -61,-30 53,30
M_DIN6 [mil]
  rect 56x56 hole 35.4: 1(-52,-26) 2(50,-26) 3(-135,-26) 5(133,-26) 6(-135,-122) 8(133,-124)
  round 137.8 hole 90.6: SH1(267,92) SH2(-1,124) SH3(-267,92)
  silkscreen extent -277,-193 275,309
MQFP-240_L32.0-W32.0-P0.50-LS34.6-BL [mm]
  rect 0.28x1.5 smd: 1(-14.75,-17.25) 2(-14.25,-17.25) 3(-13.75,-17.25) 4(-13.25,-17.25) 5(-12.75,-17.25) 6(-12.25,-17.25) 7(-11.75,-17.25) 8(-11.25,-17.25) 9(-10.75,-17.25) 10(-10.25,-17.25) 11(-9.75,-17.25) 12(-9.25,-17.25) 13(-8.75,-17.25) 14(-8.25,-17.25) 15(-7.75,-17.25) 16(-7.25,-17.25) 17(-6.75,-17.25) 18(-6.25,-17.25) 19(-5.75,-17.25) 20(-5.25,-17.25) 21(-4.75,-17.25) 22(-4.25,-17.25) 23(-3.75,-17.25) 24(-3.25,-17.25) 25(-2.75,-17.25) 26(-2.25,-17.25) 27(-1.75,-17.25) 28(-1.25,-17.25) 29(-0.75,-17.25) 30(-0.25,-17.25) 31(0.25,-17.25) 32(0.75,-17.25) 33(1.25,-17.25) 34(1.75,-17.25) 35(2.25,-17.25) 36(2.75,-17.25) 37(3.25,-17.25) 38(3.75,-17.25) 39(4.25,-17.25) 40(4.75,-17.25) 41(5.25,-17.25) 42(5.75,-17.25) 43(6.25,-17.25) 44(6.75,-17.25) 45(7.25,-17.25) 46(7.75,-17.25) 47(8.25,-17.25) 48(8.75,-17.25) 49(9.25,-17.25) 50(9.75,-17.25) 51(10.25,-17.25) 52(10.75,-17.25) 53(11.25,-17.25) 54(11.75,-17.25) 55(12.25,-17.25) 56(12.75,-17.25) 57(13.25,-17.25) 58(13.75,-17.25) 59(14.25,-17.25) 60(14.75,-17.25) 121(14.75,17.25) 122(14.25,17.25) 123(13.75,17.25) 124(13.25,17.25) 125(12.75,17.25) 126(12.25,17.25) 127(11.75,17.25) 128(11.25,17.25) 129(10.75,17.25) 130(10.25,17.25) 131(9.75,17.25) 132(9.25,17.25) 133(8.75,17.25) 134(8.25,17.25) 135(7.75,17.25) 136(7.25,17.25) 137(6.75,17.25) 138(6.25,17.25) 139(5.75,17.25) 140(5.25,17.25) 141(4.75,17.25) 142(4.25,17.25) 143(3.75,17.25) 144(3.25,17.25) 145(2.75,17.25) 146(2.25,17.25) 147(1.75,17.25) 148(1.25,17.25) 149(0.75,17.25) 150(0.25,17.25) 151(-0.25,17.25) 152(-0.75,17.25) 153(-1.25,17.25) 154(-1.75,17.25) 155(-2.25,17.25) 156(-2.75,17.25) 157(-3.25,17.25) 158(-3.75,17.25) 159(-4.25,17.25) 160(-4.75,17.25) 161(-5.25,17.25) 162(-5.75,17.25) 163(-6.25,17.25) 164(-6.75,17.25) 165(-7.25,17.25) 166(-7.75,17.25) 167(-8.25,17.25) 168(-8.75,17.25) 169(-9.25,17.25) 170(-9.75,17.25) 171(-10.25,17.25) 172(-10.75,17.25) 173(-11.25,17.25) 174(-11.75,17.25) 175(-12.25,17.25) 176(-12.75,17.25) 177(-13.25,17.25) 178(-13.75,17.25) 179(-14.25,17.25) 180(-14.75,17.25)
  rect 1.5x0.28 smd: 61(17.25,-14.75) 62(17.25,-14.25) 63(17.25,-13.75) 64(17.25,-13.25) 65(17.25,-12.75) 66(17.25,-12.25) 67(17.25,-11.75) 68(17.25,-11.25) 69(17.25,-10.75) 70(17.25,-10.25) 71(17.25,-9.75) 72(17.25,-9.25) 73(17.25,-8.75) 74(17.25,-8.25) 75(17.25,-7.75) 76(17.25,-7.25) 77(17.25,-6.75) 78(17.25,-6.25) 79(17.25,-5.75) 80(17.25,-5.25) 81(17.25,-4.75) 82(17.25,-4.25) 83(17.25,-3.75) 84(17.25,-3.25) 85(17.25,-2.75) 86(17.25,-2.25) 87(17.25,-1.75) 88(17.25,-1.25) 89(17.25,-0.75) 90(17.25,-0.25) 91(17.25,0.25) 92(17.25,0.75) 93(17.25,1.25) 94(17.25,1.75) 95(17.25,2.25) 96(17.25,2.75) 97(17.25,3.25) 98(17.25,3.75) 99(17.25,4.25) 100(17.25,4.75) 101(17.25,5.25) 102(17.25,5.75) 103(17.25,6.25) 104(17.25,6.75) 105(17.25,7.25) 106(17.25,7.75) 107(17.25,8.25) 108(17.25,8.75) 109(17.25,9.25) 110(17.25,9.75) 111(17.25,10.25) 112(17.25,10.75) 113(17.25,11.25) 114(17.25,11.75) 115(17.25,12.25) 116(17.25,12.75) 117(17.25,13.25) 118(17.25,13.75) 119(17.25,14.25) 120(17.25,14.75) 181(-17.25,14.75) 182(-17.25,14.25) 183(-17.25,13.75) 184(-17.25,13.25) 185(-17.25,12.75) 186(-17.25,12.25) 187(-17.25,11.75) 188(-17.25,11.25) 189(-17.25,10.75) 190(-17.25,10.25) 191(-17.25,9.75) 192(-17.25,9.25) 193(-17.25,8.75) 194(-17.25,8.25) 195(-17.25,7.75) 196(-17.25,7.25) 197(-17.25,6.75) 198(-17.25,6.25) 199(-17.25,5.75) 200(-17.25,5.25) 201(-17.25,4.75) 202(-17.25,4.25) 203(-17.25,3.75) 204(-17.25,3.25) 205(-17.25,2.75) 206(-17.25,2.25) 207(-17.25,1.75) 208(-17.25,1.25) 209(-17.25,0.75) 210(-17.25,0.25) 211(-17.25,-0.25) 212(-17.25,-0.75) 213(-17.25,-1.25) 214(-17.25,-1.75) 215(-17.25,-2.25) 216(-17.25,-2.75) 217(-17.25,-3.25) 218(-17.25,-3.75) 219(-17.25,-4.25) 220(-17.25,-4.75) 221(-17.25,-5.25) 222(-17.25,-5.75) 223(-17.25,-6.25) 224(-17.25,-6.75) 225(-17.25,-7.25) 226(-17.25,-7.75) 227(-17.25,-8.25) 228(-17.25,-8.75) 229(-17.25,-9.25) 230(-17.25,-9.75) 231(-17.25,-10.25) 232(-17.25,-10.75) 233(-17.25,-11.25) 234(-17.25,-11.75) 235(-17.25,-12.25) 236(-17.25,-12.75) 237(-17.25,-13.25) 238(-17.25,-13.75) 239(-17.25,-14.25) 240(-17.25,-14.75)
  silkscreen extent -16.5,-17.75 16,16
PWRM-TH_7P-L19.5-W6.0-P2.54-PE3_7 [mm]
  rect 1.6x1.6 hole 1: 1(-6.35,0)
  round 1.6 hole 1: 2(-3.81,0) 4(1.27,0) 5(3.81,0) 6(6.35,0)
  silkscreen extent -8.51,-4.5 11.02,1.52
R0603 [mil]
  rect 31.75x34.02 smd: 1(-29.66,0) 2(29.66,0)
  silkscreen extent -55,-26 55,26
R0603_NEW [mil]
  rect 31.75x34.02 smd: 1(-29.66,0) 2(29.66,0)
  silkscreen extent -55,-26 55,26
RES-ARRAY-SMD_0603-8P-L3.2-W1.6-BL [mm]
  rect 0.65x0.8 smd: 1(-1.2,-0.9) 4(1.2,-0.9) 5(1.2,0.9) 8(-1.2,0.9)
  rect 0.5x0.8 smd: 2(-0.4,-0.9) 3(0.4,-0.9) 6(0.4,0.9) 7(-0.4,0.9)
  silkscreen extent -1.87,-1.45 1.87,1.47
RES-TH_RK10J12E002L [mm]
  round 1.6 hole 1: 1(-4,-5) 2(0,-5) 3(2,-5) 4(-2,-5) 5(4,-5)
  oval 1.6x2.2 hole 0.9 slot 1.4 at 90 deg: 6(5,5) 7(-5,5)
  silkscreen extent -6.96,-5 6.96,9.46
SC-70-6_L2.2-W1.3-P0.65-LS2.1-BR [mm]
  rect 0.6x0.42 smd: 1(0.95,-0.65) 2(0.95,0) 3(0.95,0.65) 4(-0.95,0.65) 5(-0.95,0) 6(-0.95,-0.65)
  silkscreen extent -0.7,-1.34 1.22,1.1
SD-SMD_SD-101 [mm]
  rect 1x2 smd: 1(6.87,8.275) 2(4.37,8.275) 3(1.87,8.275) 4(-0.63,8.275) 5(-3.13,8.275) 6(-5.63,8.275) 7(-8.06,8.275) 8(-9.76,8.275) 9(9.37,8.275)
  rect 0.7x2 smd: 10(-11.06,8.275) 11(-12.26,8.275)
  rect 1.5x2.8 smd: 12(-13.65,6.325) 13(-13.65,-8.175) 14(13.65,-8.275) 15(11.45,6.225)
  Multi-Layer board cut-out: 8.65,5.225 8.767,4.804 9.077,4.496 9.5,4.383 9.923,4.496 10.233,4.803 10.35,5.225 10.35,5.225 10.233,5.647 9.923,5.954 9.5,6.067 9.077,5.954 8.767,5.647 8.65,5.225
  Multi-Layer board cut-out: -12.1,5.275 -12.041,5.015 -11.874,4.806 -11.634,4.69 -11.367,4.69 -11.126,4.806 -10.959,5.014 -10.9,5.275 -10.9,5.275 -10.959,5.535 -11.126,5.744 -11.366,5.86 -11.633,5.86 -11.874,5.744 -12.041,5.535 -12.1,5.275
  Multi-Layer keep-out region: 8.65,5.225 8.767,4.804 9.077,4.496 9.5,4.383 9.923,4.496 10.233,4.803 10.35,5.225 10.35,5.225 10.233,5.647 9.923,5.954 9.5,6.067 9.077,5.954 8.767,5.647 8.65,5.225
  Multi-Layer keep-out region: -12.1,5.275 -12.041,5.015 -11.874,4.806 -11.634,4.69 -11.367,4.69 -11.126,4.806 -10.959,5.014 -10.9,5.275 -10.9,5.275 -10.959,5.535 -11.126,5.744 -11.366,5.86 -11.633,5.86 -11.874,5.744 -12.041,5.535 -12.1,5.275
  silkscreen extent -13.2,-9.27 13.2,7.23
SMA_L4.2-W2.6-LS5.3-RD [mm]
  rect 2.2x1.7 smd: 1(-2.565,0) 2(2.565,0)
  silkscreen extent -3.08,-1.44 2.7,1.44
SOIC-8_L5.0-W4.0-P1.27-LS6.0-BL [mil]
  oval 22.38x76.78 smd: 1(-75,-106.5) 2(-25,-106.5) 3(25,-106.5) 4(75,-106.5) 5(75,106.5) 6(25,106.5) 7(-25,106.5) 8(-75,106.5)
  silkscreen extent -106,-111 98,75
SOP-8_L4.9-W3.8-P1.27-LS6.0-BL [mil]
  oval 25.59x80 smd: 1(-75,-110.08) 2(-25,-110.08) 3(25,-110.08) 4(75,-110.08) 5(75,110.08) 6(25,110.08) 7(-25,110.08) 8(-75,110.08)
  silkscreen extent -108,-85 101,57
SOP-8_L4.9-W3.9-P1.27-LS6.0-BL [mm]
  oval 0.63x1.865 smd: 1(-1.905,-2.682) 2(-0.635,-2.682) 3(0.635,-2.682) 4(1.905,-2.682) 5(1.905,2.682) 6(0.635,2.682) 7(-0.635,2.682) 8(-1.905,2.682)
  silkscreen extent -2.82,-2.83 2.58,1.52
SOT-223-3_L6.5-W3.4-P2.30-LS7.0-BR [mm]
  rect 2.5x1.1 smd: 1(2.97,-2.3) 2(2.97,0) 3(2.97,2.3)
  rect 2.34x3.6 smd: 4(-2.97,0)
  silkscreen extent -1.57,-3.33 1.37,3.33
SOT-223_L6.3-W3.5-P2.30-LS7.0-BR [mm]
  rect 2.465x1.05 smd: 1(2.857,-2.3) 2(2.857,0) 3(2.858,2.3)
  rect 2.465x3.54 smd: 4(-2.857,0)
  silkscreen extent -1.4,-3.4 1.4,3.4
SW-TH_DP-08XP [mm]
  round 1.6 hole 1: 1(-8.887,-3.823) 2(-6.347,-3.823) 3(-3.807,-3.823) 4(-1.267,-3.823) 5(1.26,-3.818) 6(3.807,-3.797) 7(6.347,-3.797) 8(8.887,-3.797) 9(8.887,3.823) 10(6.347,3.823) 11(3.807,3.823) 12(1.26,3.802) 13(-1.267,3.797) 14(-3.807,3.797) 15(-6.347,3.797) 16(-8.887,3.797)
  silkscreen extent -11.05,-7.19 11.06,5.34
SW-TH_PS-12E051XX [mm]
  oval 1.3x1.2 hole 0.8 slot 0.9 at 0 deg: 1(-2.4,-0.55) 2(0.1,-0.55) 3(2.6,-0.55)
  oval 1.4x1.6 hole 1 slot 1.2 at 90 deg: 4(-5.7,-1.65)
  oval 1.6x1.4 hole 1 slot 1.2 at 0 deg: 4(5.7,1.65)
  silkscreen extent -6.13,-3.1 16.31,2
S端子母座 [mil]
  round 60 hole 36 copper offset -0.01,0.01: 1(43.36,-97.28) 2(-59,-97.28)
  round 60 hole 36: 3(124.07,-97.28) 4(-139.71,-97.28) 5(124.07,-195.31) 6(-139.71,-195.31)
  oval 70.87x141.73 hole 35.43 slot 94.49 at 90 deg: 7(284.48,10.79) 9(-300.52,10.79)
  oval 141.73x70.87 hole 35.43 slot 94.49 at 0 deg: 8(-5.25,65.91)
  silkscreen extent -283,-266 268,238
TF-SMD_TF-012 [mm]
  rect 0.7x1.6 smd: 1(2.25,5.3) 2(1.15,5.3) 3(0.05,5.3) 4(-1.05,5.3) 5(-2.15,5.3) 6(-3.25,5.3) 7(-4.35,5.3) 8(-5.45,5.3) CD(-6.55,5.3)
  rect 1.2x1.5 smd: 10(-7.8,4.3)
  rect 1.2x2.2 smd: 11(-7.8,-5.3) 12(7.8,-5.3)
  rect 1.6x1.5 smd: 13(6.85,4.3)
  Multi-Layer board cut-out: -5.45,-5.7 -5.4,-5.917 -5.262,-6.091 -5.061,-6.188 -4.839,-6.188 -4.638,-6.091 -4.499,-5.917 -4.45,-5.7 -4.45,-5.7 -4.499,-5.483 -4.638,-5.309 -4.839,-5.213 -5.061,-5.213 -5.262,-5.309 -5.4,-5.483 -5.45,-5.7
  Multi-Layer board cut-out: 2.55,-5.7 2.6,-5.917 2.738,-6.091 2.939,-6.188 3.161,-6.188 3.362,-6.091 3.501,-5.917 3.55,-5.7 3.55,-5.7 3.501,-5.483 3.362,-5.309 3.161,-5.213 2.939,-5.213 2.738,-5.309 2.6,-5.483 2.55,-5.7
  Multi-Layer keep-out region: -5.45,-5.7 -5.4,-5.917 -5.262,-6.091 -5.061,-6.188 -4.839,-6.188 -4.638,-6.091 -4.499,-5.917 -4.45,-5.7 -4.45,-5.7 -4.499,-5.483 -4.638,-5.309 -4.839,-5.213 -5.061,-5.213 -5.262,-5.309 -5.4,-5.483 -5.45,-5.7
  Multi-Layer keep-out region: 2.55,-5.7 2.6,-5.917 2.738,-6.091 2.939,-6.188 3.161,-6.188 3.362,-6.091 3.501,-5.917 3.55,-5.7 3.55,-5.7 3.501,-5.483 3.362,-5.309 3.161,-5.213 2.939,-5.213 2.738,-5.309 2.6,-5.483 2.55,-5.7
  silkscreen extent -7.58,-9.83 7.57,5.31
TSOP54 [mil]
  rect 15.7x63 smd: 1(-409,-215) 2(-378,-215) 3(-346.05,-215) 4(-314.97,-215) 5(-283,-215) 6(-252,-215) 7(-219.97,-215) 8(-189,-215) 9(-157,-215) 10(-126.05,-215) 11(-94,-215) 12(-63,-215) 13(-31.05,-215) 14(0.03,-215) 15(31,-215) 16(63,-215) 17(93.95,-215) 18(126,-215) 19(157,-215) 20(188.95,-215) 21(220.03,-215) 22(252,-215) 23(283.05,-215) 24(315.03,-215) 25(346.05,-215) 26(378.05,-215) 27(409,-215) 28(408.95,215) 29(378,215) 30(346,215) 31(315.03,215) 32(283,215) 33(252,215) 34(220.03,215) 35(188.95,215) 36(157,215) 37(126,215) 38(93.95,215) 39(63,215) 40(31,215) 41(0.03,215) 42(-31.05,215) 43(-63,215) 44(-94,215) 45(-126.05,215) 46(-157,215) 47(-189,215) 48(-219.97,215) 49(-252,215) 50(-283,215) 51(-314.97,215) 52(-346.05,215) 53(-378,215) 54(-409,215)
  silkscreen extent -441,-205 441,205
TYPE-C-SMD_TYPE-C-6P [mm]
  oval 1.1x1.9 hole 0.7 slot 1.5 at 90 deg: 7(-4.32,-1.9) 7(-4.32,1.9) 7(4.32,-1.9) 7(4.32,1.9)
  rect 0.7x1.2 smd: A5(-0.5,1.9) A9(1.5,1.9) B5(0.5,1.9) B9(-1.5,1.9)
  rect 0.8x1.2 smd: A12(2.7,1.9) B12(-2.7,1.9)
  silkscreen extent -4.5,-4.5 4.5,2.3
USB-A-TH_USB-M-51 [mm]
  round 1.7 hole 1.1: 1(-3.5,2.574) 2(-1.001,2.574) 3(1.001,2.574) 4(3.5,2.574) 5(-3.5,-0.027) 6(-1.001,-0.027) 7(1.001,-0.027) 8(3.5,-0.027)
  round 3.2 hole 2.3: 9(-6.551,-2.925) 9(-6.551,2.925) 9(6.551,-2.826) 9(6.551,2.925)
  silkscreen extent -7.52,-14.13 7.54,3.87

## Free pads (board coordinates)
  round 236.22 hole 137.8: 1(6247.01,3542.05) 1(7072.01,7142.05) 1(9847.01,3542.05) 1(9847.01,6642.05) 1(10635,3542.05) 1(10635,7167.05) 1(12135,3542.05) 1(12135,7167.05)

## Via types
v1: diameter 20, hole 12, Top Layer to Bottom Layer, 944 vias
v2: diameter 24, hole 12, Top Layer to Bottom Layer, 2 vias

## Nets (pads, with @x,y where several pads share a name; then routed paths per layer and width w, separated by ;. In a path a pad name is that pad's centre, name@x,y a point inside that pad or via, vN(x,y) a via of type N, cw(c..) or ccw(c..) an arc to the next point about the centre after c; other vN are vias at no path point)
5V-IN: 5V-IN.2 DC1.1 H3.45 H5.46 U14.1 | length 5781.6
  Top Layer w6: 5V-IN.2@5010.2,7246.55 5045.7,7282.05 5525,7282.05 5550,7257.05 5550,6642.05 5525,6617.05 5435,6617.05 H3.45@5385,6567.05
  Top Layer w10: H5.46@9022.01,6567.05 9072.01,6617.05 9215,6617.05 9485,6347.05 9485,6237.05 9505,6217.05 9765,6217.05 9835,6147.05 9835,3927.05 9775,3867.05 9543.86,3867.05 U14.1@9413.35,3736.53
  Top Layer w66.93: U14.1@9413.35,3736.53 9360.52,3736.53 9260,3837.05 9125.3,3837.05 ; 9125.3,3837.05 9073.41,3785.16 DC1.1@9015.51,3785.16 9067.4,3837.05 9125.3,3837.05
$1N379: C23.1 R12.1 U8.154 | length 852.9
  Top Layer w6: v1(4432.5,5417.05) 4501.4,5485.95 U8.154@5114.14,5485.95
  Bottom Layer w6: R12.1@4339.66,5367.05 C23.1@4432.45,5367.05 ; C23.1@4432.5,5367.1 v1(4432.5,5417.05)
$1N734: R9.1 R10.1 U1.6 | length 1582.2
  Bottom Layer w6: R10.1@4064.66,5417.05 R9.1@4064.66,5492.05 4064.66,5787.39 3912.5,5939.55 3912.5,6652.74 4109.41,6849.65 U1.6@4109.41,6854.65
$1N2047: C2.2 R3.1 U1.3 U3.1 | length 283.6
  Bottom Layer w6: U1.3@4160.59,6929.45 4180.59,6949.45 4197.06,6949.45 R3.1@4239.66,6992.05 4239.66,7158.45 U3.1@4231.06,7167.05
$1N12195: C22.1 R11.1 U8.27 | length 768.9
  Top Layer w6: U8.27@3755.86,5485.95 3963.9,5485.95 3980,5502.05 4255,5502.05 v1(4340,5417.05)
  Bottom Layer w6: v1(4340,5417.05) 4340,5466.71 R11.1@4339.66,5467.05 C22.1@4432.45,5467.05
$1N16804: R3.2 R4.2 U1.1 U1.4 | length 263.1
  Bottom Layer w6: U1.4@4160.59,6854.65 4160.59,6871.46 4127.5,6904.55 4117.91,6904.55 4109.41,6913.05 U1.1@4109.41,6929.45 4109.41,6932.3 4089.66,6952.05 R4.2@4089.66,6992.05 R3.2@4180.34,6992.05
$1N16805: C5.2 R4.1 U3.2 | length 178.6
  Bottom Layer w6: R4.1@4030.34,6992.05 4030.34,7158.45 U3.2@4038.94,7167.05
$1N39791: 5V-IN.1 R5.1 | length 87
  Top Layer w6: R5.1@5010,7096.71 5010.4,7097.11 5V-IN.1@5010.4,7183.55
$1N39793: 5V.1@4885.4,7183.55 R6.1 | length 87
  Top Layer w6: R6.1@4885,7096.71 4885.4,7097.11 5V.1@4885.4,7183.55
$1N39797: 3.3V.1 R7.1 | length 87
  Top Layer w6: R7.1@4760,7096.71 4760.4,7097.11 3.3V.1@4760.4,7183.55
$1N39803: 1.5V.1 R8.1 | length 87
  Top Layer w6: R8.1@4635,7096.71 4635.4,7097.11 1.5V.1@4635.4,7183.55
$1N46954: R13.1 U8.38 | length 259.2
  Top Layer w6: U8.38@3755.86,5269.41 3912.36,5269.41 v1(3985,5342.05)
$2N2106: C36.2 SLOT1.49 | length 506.8
  Top Layer w10: v1(11835,6467.05) 11982.44,6319.61 C36.2@11982.44,6317.05
  Bottom Layer w10: SLOT1.49@11560,6517.07 11634.98,6517.07 11685,6467.05 v1(11835,6467.05)
$2N2130: C37.2 SLOT2.49 | length 706.8
  Top Layer w10: C37.2@12262.56,6317.05 12262.56,6319.61 v1(12410,6467.05)
  Bottom Layer w10: v1(12410,6467.05) 12834.98,6467.05 SLOT2.49@12885,6517.07
$2N2392: 5V.2@10614.5,6541.85 R42.2 | length 124.3
  Top Layer w10: R42.2@10555.34,6442.05 10555.34,6482.69 5V.2@10614.5,6541.85
$2N2395: -12V.2 R43.2 | length 124.3
  Top Layer w10: R43.2@10555.34,6642.05 10555.34,6682.69 -12V.2@10614.5,6741.85
$2N2398: +12V.2 R44.2 | length 124.3
  Top Layer w10: R44.2@10555.34,6842.05 10555.34,6882.69 +12V.2@10614.5,6941.85
$4N317: LED13.2 R34.2 | length 100.3
  Top Layer w10: LED13.2@6489.5,3916.85 6489.5,4016.89 R34.2@6489.66,4017.05
$4N8313: R16.2 USB1.2 | length 172.7
  Top Layer w10: USB1.2@6536.41,6690.7 6536.41,6600.98 6570.34,6567.05 R16.2@6605.34,6567.05
$4N8314: R17.2 USB1.3 | length 297.9
  Top Layer w10: USB1.3@6457.61,6690.7 6457.61,6574.78 6540.34,6492.05 R17.2@6605.34,6492.05
$4N8492: C24.1 KEY1.2 U13.5 | length 462
  Bottom Layer w10: KEY1.2@6185,3828.47 6246.02,3889.49 C24.1@6285,3889.49 6477.36,3889.49 6529.92,3942.05 U13.5@6599.92,3942.05
$4N8660: D1.2 U14.2 | length 216.1
  Top Layer w66.93: U14.2@9413.35,3638.11 9562.94,3638.11 D1.2@9610,3591.05
$4N8663: D1.1 U15.1 | length 168.5
  Top Layer w66.93: D1.1@9610,3793.05 9611,3792.05 U15.1@9778.11,3792.05
$4N10687: C26.2 RN28.6 RN36.3 | length 337.4
  Top Layer w10: v1(8570,4692.05) 8685,4807.05 v1(8685,4837.05)
  Bottom Layer w10: RN28.6@8569.25,4652.48 RN36.3@8569.25,4731.61 ; v1(8685,4837.05) C26.2@8685,4902.68
$4N10692: C25.2 RN27.8 RN35.1 | length 267.9
  Bottom Layer w10: RN27.8@8832.24,4652.48 RN35.1@8832.24,4731.61 8875,4774.37 C25.2@8875,4902.68
$4N10755: R24.1 RN36.7 | length 110.2
  Bottom Layer w10: R24.1@8600,4912.39 8600.75,4911.64 RN36.7@8600.75,4802.48
$4N10758: R25.1 RN37.5 | length 110.8
  Bottom Layer w10: RN37.5@8337.76,4802.48 8337.76,4910.15 R25.1@8340,4912.39
$4N10767: C35.2 R41.1 | length 84.7
  Top Layer w10: C35.2@7844.37,5137.05 7855,5147.68 R41.1@7855,5217.39
$4N10768: C33.1 U18.3 | length 258.3
  Top Layer w10: U18.3@7978.39,5291.94 8060.11,5291.94 8112.45,5239.59 8112.45,5137.15 C33.1@8112.55,5137.05
$4N10775: CN2.4 R33.1 R36.2 | length 2123.3
  Top Layer w10: CN2.4@7166.89,3758.19 7196.89,3758.19 7225,3786.3 v1(7225,4327.05) ; R33.1@7755,5276.71 v1(7755,5317.05) R36.2@7755,5357.39
  Bottom Layer w10: v1(7225,4327.05) 7225,5167.05 7375,5317.05 v1(7755,5317.05)
$4N10776: CN2.3 R32.1 R35.2 | length 3056.9
  Top Layer w10: CN2.3@7166.89,3600.71 7136.89,3600.71 7080,3657.6 7080,3797.05 7200,3917.05 v1(7200,4307.05) ; R32.1@8415,5276.71 v1(8415,5317.05) R35.2@8415,5357.39
  Bottom Layer w10: v1(7200,4307.05) 7200,5182.05 7360,5342.05 8390,5342.05 v1(8415,5317.05)
$4N10777: C31.1 R36.1 | length 84.7
  Top Layer w10: R36.1@7755,5416.71 7755,5486.42 C31.1@7765.63,5497.05
$4N10778: C30.2 R35.1 | length 84.7
  Top Layer w10: C30.2@8404.37,5497.05 8415,5486.42 R35.1@8415,5416.71
$4N10779: C31.2 R38.2 U18.1 | length 218.5
  Top Layer w10: C31.2@7844.37,5497.05 7855,5486.42 R38.2@7855,5416.71 7879.66,5392.05 U18.1@7978.5,5392.05
$4N10780: R38.1 R41.2 U18.2 | length 204.7
  Top Layer w10: R41.2@7855,5276.71 7855,5340.68 ; R38.1@7855,5357.39 7855,5340.68 ; U18.2@7978.5,5342.05 7856.37,5342.05 7855,5340.68
$4N10781: C30.1 R37.2 U18.7 | length 239.2
  Top Layer w10: U18.7@8191.5,5342.05 8235.34,5342.05 8310,5416.71 R37.2@8315,5416.71 8315,5486.42 C30.1@8325.63,5497.05
$4N10782: R37.1 R40.1 U18.6 | length 204.4
  Top Layer w10: U18.6@8191.5,5292.05 8314.58,5292.05 R40.1@8315,5292.47 ; R40.1@8315,5276.71 R40.1@8315,5292.47 ; R37.1@8315,5357.39 R40.1@8315,5292.47
$4N10785: C35.1 R39.4 | length 2578.4
  Bottom Layer w10: v1(7735,5137.05) 8385,5137.05 8775,5527.05 8775,6732.83 8856.26,6814.09 R39.4@8856.26,6870.19
$4N10787: C34.1 R40.2 | length 84.7
  Top Layer w10: R40.2@8315,5217.39 8315,5147.68 C34.1@8325.63,5137.05
$4N10789: C34.2 R39.2 | length 1940.3
  Bottom Layer w10: v1(8435,5137.05) 8435,5159.42 8796,5520.42 8796,6721.2 8935,6860.2 R39.2@8935,6870.19
$4N11161: RN27.7 RN35.2 RN35.8 | length 163
  Bottom Layer w10: RN27.7@8800.75,4652.48 RN35.2@8800.75,4731.61 8800.75,4749.81 8832.24,4781.3 RN35.8@8832.24,4802.48
$4N11167: RN27.6 RN35.3 RN35.7 | length 163
  Bottom Layer w10: RN27.6@8769.25,4652.48 RN35.3@8769.25,4731.61 8769.26,4749.81 8800.75,4781.3 RN35.7@8800.75,4802.48
$4N11173: RN27.5 RN35.4 RN35.6 | length 163
  Bottom Layer w10: RN27.5@8737.76,4652.48 RN35.4@8737.76,4731.61 8737.76,4749.81 8769.25,4781.3 RN35.6@8769.25,4802.48
$4N11234: RN28.8 RN35.5 RN36.1 | length 214
  Bottom Layer w10: RN28.8@8632.24,4652.48 RN36.1@8632.24,4731.61 8703.11,4802.48 RN35.5@8737.76,4802.48
$4N11240: RN28.7 RN36.2 RN36.8 | length 163
  Bottom Layer w10: RN28.7@8600.75,4652.48 RN36.2@8600.75,4731.61 8600.75,4749.81 8632.24,4781.3 RN36.8@8632.24,4802.48
$4N11246: RN28.5 RN36.4 RN36.6 | length 163
  Bottom Layer w10: RN28.5@8537.76,4652.48 RN36.4@8537.76,4731.61 8537.76,4749.81 8569.25,4781.3 RN36.6@8569.25,4802.48
$4N11293: RN29.8 RN36.5 RN37.1 | length 214
  Bottom Layer w10: RN29.8@8432.24,4652.48 RN37.1@8432.24,4731.61 8503.11,4802.48 RN36.5@8537.76,4802.48
$4N11301: RN29.7 RN37.2 RN37.8 | length 163
  Bottom Layer w10: RN29.7@8400.75,4652.48 RN37.2@8400.75,4731.61 8400.75,4749.81 8432.24,4781.3 RN37.8@8432.24,4802.48
$4N11306: RN29.6 RN37.3 RN37.7 | length 163
  Bottom Layer w10: RN29.6@8369.25,4652.48 RN37.3@8369.25,4731.61 8369.26,4749.81 8400.75,4781.3 RN37.7@8400.75,4802.48
$4N11311: RN29.5 RN37.4 RN37.6 | length 163
  Bottom Layer w10: RN29.5@8337.76,4652.48 RN37.4@8337.76,4731.61 8337.76,4749.81 8369.25,4781.3 RN37.6@8369.25,4802.48
$4N12254: C29.1 RN32.6 RN40.3 | length 872
  Top Layer w10: v1(7570,4692.05) 7745,4692.05 7885,4552.05 C29.1@7885,4132.16
  Bottom Layer w10: RN32.6@7569.25,4652.48 RN40.3@7569.25,4731.61
$4N12288: R28.1 RN41.5 | length 110.8
  Bottom Layer w10: RN41.5@7337.76,4802.48 7337.76,4910.15 R28.1@7340,4912.39
$4N12294: RN32.5 RN40.4 RN40.6 | length 163
  Bottom Layer w10: RN32.5@7537.76,4652.48 RN40.4@7537.76,4731.61 7537.76,4749.81 7569.25,4781.3 RN40.6@7569.25,4802.48
$4N12299: RN33.8 RN40.5 RN41.1 | length 214
  Bottom Layer w10: RN33.8@7432.24,4652.48 RN41.1@7432.24,4731.61 7503.11,4802.48 RN40.5@7537.76,4802.48
$4N12304: RN33.7 RN41.2 RN41.8 | length 163
  Bottom Layer w10: RN33.7@7400.75,4652.48 RN41.2@7400.75,4731.61 7400.75,4749.81 7432.24,4781.3 RN41.8@7432.24,4802.48
$4N12313: RN33.6 RN41.3 RN41.7 | length 163
  Bottom Layer w10: RN33.6@7369.25,4652.48 RN41.3@7369.25,4731.61 7369.26,4749.81 7400.75,4781.3 RN41.7@7400.75,4802.48
$4N12318: RN33.5 RN41.4 RN41.6 | length 163
  Bottom Layer w10: RN33.5@7337.76,4652.48 RN41.4@7337.76,4731.61 7337.76,4749.81 7369.25,4781.3 RN41.6@7369.25,4802.48
$4N12766: C27.1 R18.2 R20.1 | length 828.5
  Top Layer w10: v1(8210,4692.05) 8345,4692.05 8485,4552.05 C27.1@8485,4147.16
  Bottom Layer w10: R18.2@8210,4646.71 v1(8210,4692.05) R20.1@8210,4737.39
$4N12770: R19.2 R20.2 R21.1 | length 190.3
  Bottom Layer w10: R19.2@8135,4646.71 R21.1@8135,4737.39 8165,4767.39 8180.68,4767.39 R20.2@8210,4796.71
$4N12775: R21.2 RN30.8 RN38.1 | length 214
  Bottom Layer w10: RN30.8@8032.24,4652.48 RN38.1@8032.24,4731.61 8103.11,4802.48 R21.2@8137.76,4802.48
$4N12780: RN30.7 RN38.2 RN38.8 | length 163
  Bottom Layer w10: RN30.7@8000.75,4652.48 RN38.2@8000.75,4731.61 8000.75,4749.81 8032.24,4781.3 RN38.8@8032.24,4802.48
$4N12785: RN30.6 RN38.3 RN38.7 | length 163
  Bottom Layer w10: RN30.6@7969.25,4652.48 RN38.3@7969.25,4731.61 7969.26,4749.81 8000.75,4781.3 RN38.7@8000.75,4802.48
$4N12790: RN30.5 RN38.4 RN38.6 | length 163
  Bottom Layer w10: RN30.5@7937.76,4652.48 RN38.4@7937.76,4731.61 7937.76,4749.81 7969.25,4781.3 RN38.6@7969.25,4802.48
$4N12834: R26.1 RN38.5 | length 110.8
  Bottom Layer w10: RN38.5@7937.76,4802.48 7937.76,4910.15 R26.1@7940,4912.39
$4N23355: R27.1 RN40.7 | length 110.2
  Bottom Layer w10: R27.1@7600,4912.39 7600.75,4911.64 RN40.7@7600.75,4802.48
$4N23356: C28.1 RN31.8 RN39.1 | length 892
  Top Layer w10: v1(7835,4692.05) 8045,4692.05 8185,4552.05 C28.1@8184.99,4147.16
  Bottom Layer w10: RN31.8@7832.24,4652.48 RN39.1@7832.24,4731.61
$4N23357: RN31.7 RN39.2 RN39.8 | length 163
  Bottom Layer w10: RN31.7@7800.75,4652.48 RN39.2@7800.75,4731.61 7800.75,4749.81 7832.24,4781.3 RN39.8@7832.24,4802.48
$4N23358: RN31.6 RN39.3 RN39.7 | length 163
  Bottom Layer w10: RN31.6@7769.25,4652.48 RN39.3@7769.25,4731.61 7769.26,4749.81 7800.75,4781.3 RN39.7@7800.75,4802.48
$4N23359: RN31.5 RN39.4 RN39.6 | length 163
  Bottom Layer w10: RN31.5@7737.76,4652.48 RN39.4@7737.76,4731.61 7737.76,4749.81 7769.25,4781.3 RN39.6@7769.25,4802.48
$4N23360: RN32.8 RN39.5 RN40.1 | length 214
  Bottom Layer w10: RN32.8@7632.24,4652.48 RN40.1@7632.24,4731.61 7703.11,4802.48 RN39.5@7737.76,4802.48
$4N23361: RN32.7 RN40.2 RN40.8 | length 163
  Bottom Layer w10: RN32.7@7600.75,4652.48 RN40.2@7600.75,4731.61 7600.75,4749.81 7632.24,4781.3 RN40.8@7632.24,4802.48
A0: H7.20 RN19.7 SLOT1.28 SLOT2.28 U10.6 | length 2504.8
  Bottom Layer w6: RN19.7@9320.43,5751.3 9345.75,5751.3 9367,5730.05 9367,5647.02 9427,5587.02 9427,5467.02 9526.97,5367.05 U10.6@9535,5367.05
  Bottom Layer w10: H7.20@10735,5367.05 11235,5367.05 11285,5417.05 11359.98,5417.05 11435.02,5417.07 11485,5467.05 11635,5467.05 11684.98,5417.07 SLOT2.28@12685,5417.07
A1: H7.19 RN19.8 SLOT1.27 SLOT2.27 U10.5 | length 3008
  Bottom Layer w6: RN19.8@9320.43,5719.81 9347.24,5719.81 9355,5712.05 9355,5642.05 9415,5582.05 9415,5462.05 9476,5401.05 9476,5331.05 9490,5317.05 9585,5317.05 U10.5@9635,5367.05
  Bottom Layer w10: H7.19@10635,5367.05 10685,5317.05 11235,5317.05 11285,5367.05 11435,5367.05 11485.02,5417.07 SLOT1.27@11560,5417.07 11634.98,5417.07 11685,5367.05 12834.98,5367.05 SLOT2.27@12885,5417.07
A2: H7.18 RN19.5 SLOT1.30 SLOT2.30 U10.8 | length 2503.5
  Bottom Layer w6: RN19.5@9320.43,5814.29 9347.76,5814.29 9391,5771.05 9391,5656.96 9451,5596.96 9451,5476.96 9460.91,5467.05 U10.8@9535,5467.05
  Bottom Layer w10: H7.18@10735,5467.05 11235,5467.05 11285,5517.05 11359.98,5517.05 11435.02,5517.07 11480,5562.05 11635,5562.05 11679.98,5517.07 SLOT2.30@12685,5517.07
A3: H7.17 RN19.6 SLOT1.29 SLOT2.29 U10.7 | length 2968.7
  Bottom Layer w6: RN19.6@9320.43,5782.8 9347.28,5782.8 9379,5751.08 9379,5651.99 9439,5591.99 9439,5471.99 9493.94,5417.05 9585,5417.05 U10.7@9635,5467.05
  Bottom Layer w10: H7.17@10635,5467.05 10685,5417.05 11235,5417.05 11285,5467.05 11435,5467.05 11485.02,5517.07 SLOT1.29@11560,5517.07 11634.98,5517.07 11685,5467.05 12834.98,5467.05 SLOT2.29@12885,5517.07
A4: H7.16 RN18.7 SLOT1.32 SLOT2.32 U10.10 | length 2507.1
  Bottom Layer w6: RN18.7@9320.43,5951.3 9345.75,5951.3 9367,5930.05 9367,5847.02 9427,5787.02 9427,5663.02 9522.98,5567.05 U10.10@9535,5567.05
  Bottom Layer w10: H7.16@10735,5567.05 11235,5567.05 11285,5617.05 11359.98,5617.05 11435.02,5617.07 11485,5667.05 11635,5667.05 11684.98,5617.07 SLOT2.32@12685,5617.07
A5: H7.15 RN18.8 SLOT1.31 SLOT2.31 U10.9 | length 3005.1
  Bottom Layer w6: RN18.8@9320.43,5919.81 9347.24,5919.81 9355,5912.05 9355,5842.05 9415,5782.05 9415,5658.05 9473,5600.05 9473,5539.05 9495,5517.05 9585,5517.05 U10.9@9635,5567.05
  Bottom Layer w10: H7.15@10635,5567.05 10685,5517.05 11235,5517.05 11285,5567.05 11435,5567.05 11485.02,5617.07 SLOT1.31@11560,5617.07 11634.98,5617.07 11685,5567.05 12834.98,5567.05 SLOT2.31@12885,5617.07
A6: H7.26 RN21.5 SLOT1.22 SLOT2.22 U9.24 | length 2505.9
  Bottom Layer w6: RN21.5@9320.43,5414.29 9347.76,5414.29 9391,5371.05 9391,5256.96 9451,5196.96 9451,5079.84 9463.79,5067.05 U9.24@9535,5067.05
  Bottom Layer w10: H7.26@10735,5067.05 11235,5067.05 11285,5117.05 SLOT1.22@11359.97,5117.05 ; SLOT1.22@11360,5117.08 11435.03,5117.08 11485,5167.05 11635.01,5167.05 11684.98,5117.08 SLOT2.22@12685,5117.08
A7: H7.25 RN21.6 SLOT1.21 SLOT2.21 U9.23 | length 2967.4
  Bottom Layer w6: RN21.6@9320.43,5382.8 9348,5382.8 9379,5351.8 9379,5251.99 9439,5191.99 9439,5074.87 9496.82,5017.05 9585,5017.05 U9.23@9635,5067.05
  Bottom Layer w10: H7.25@10635,5067.05 10685,5017.05 11235,5017.05 11285,5067.05 11435,5067.05 11485.03,5117.08 SLOT1.21@11560,5117.08 11634.97,5117.08 11685,5067.05 12834.97,5067.05 SLOT2.21@12885,5117.08
A8: H7.24 RN20.7 SLOT1.24 SLOT2.24 U10.2 | length 2508.5
  Bottom Layer w6: RN20.7@9320.43,5551.3 9345.75,5551.3 9366,5531.05 9366,5448.02 9427,5387.02 9427,5266.56 9530.76,5162.81 U10.2@9535,5167.05
  Bottom Layer w10: H7.24@10735,5167.05 11235,5167.05 11285,5217.05 SLOT1.24@11359.97,5217.05 ; SLOT1.24@11360,5217.08 11435.03,5217.08 11485,5267.05 11635.01,5267.05 11684.98,5217.08 SLOT2.24@12685,5217.08
A9: H7.31 RN22.8 SLOT1.17 SLOT2.17 U9.17 | length 3046.5
  Bottom Layer w6: RN22.8@9320.43,5119.81 9347.24,5119.81 9355,5112.05 9355,5042.05 9420,4977.05 9420,4854.93 9477.01,4797.92 9477.01,4735.03 9495,4717.05 9585,4717.05 U9.17@9635,4767.05
  Bottom Layer w10: H7.31@10635,4767.05 10685,4717.05 11136.97,4717.05 11286.97,4867.05 11435,4867.05 11485.03,4917.08 SLOT1.17@11560,4917.08 11634.97,4917.08 11685,4867.05 12834.97,4867.05 SLOT2.17@12885,4917.08
A10: H7.30 RN22.5 SLOT1.20 SLOT2.20 U9.20 | length 2543.7
  Bottom Layer w6: RN22.5@9320.43,5214.29 9347.76,5214.29 9391,5171.05 9391,5056.96 9456,4991.96 9456,4881.05 9470,4867.05 U9.20@9535,4867.05
  Bottom Layer w10: H7.30@10735,4867.05 11135,4867.05 11285.03,5017.08 SLOT1.20@11360,5017.08 11435.03,5017.08 11485,5067.05 11635,5067.05 11684.97,5017.08 SLOT2.20@12685,5017.08
A11: H7.29 RN22.6 SLOT1.19 SLOT2.19 U9.19 | length 3012.5
  Bottom Layer w6: RN22.6@9320.43,5182.8 9349.25,5182.8 9379,5153.05 9379,5051.99 9444,4986.99 9444,4864.87 9491.82,4817.05 9585,4817.05 U9.19@9635,4867.05
  Bottom Layer w10: H7.29@10635,4867.05 10685,4817.05 11136.97,4817.05 11286.97,4967.05 11435,4967.05 11485.03,5017.08 SLOT1.19@11560,5017.08 11634.97,5017.08 11685,4967.05 12834.97,4967.05 SLOT2.19@12885,5017.08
